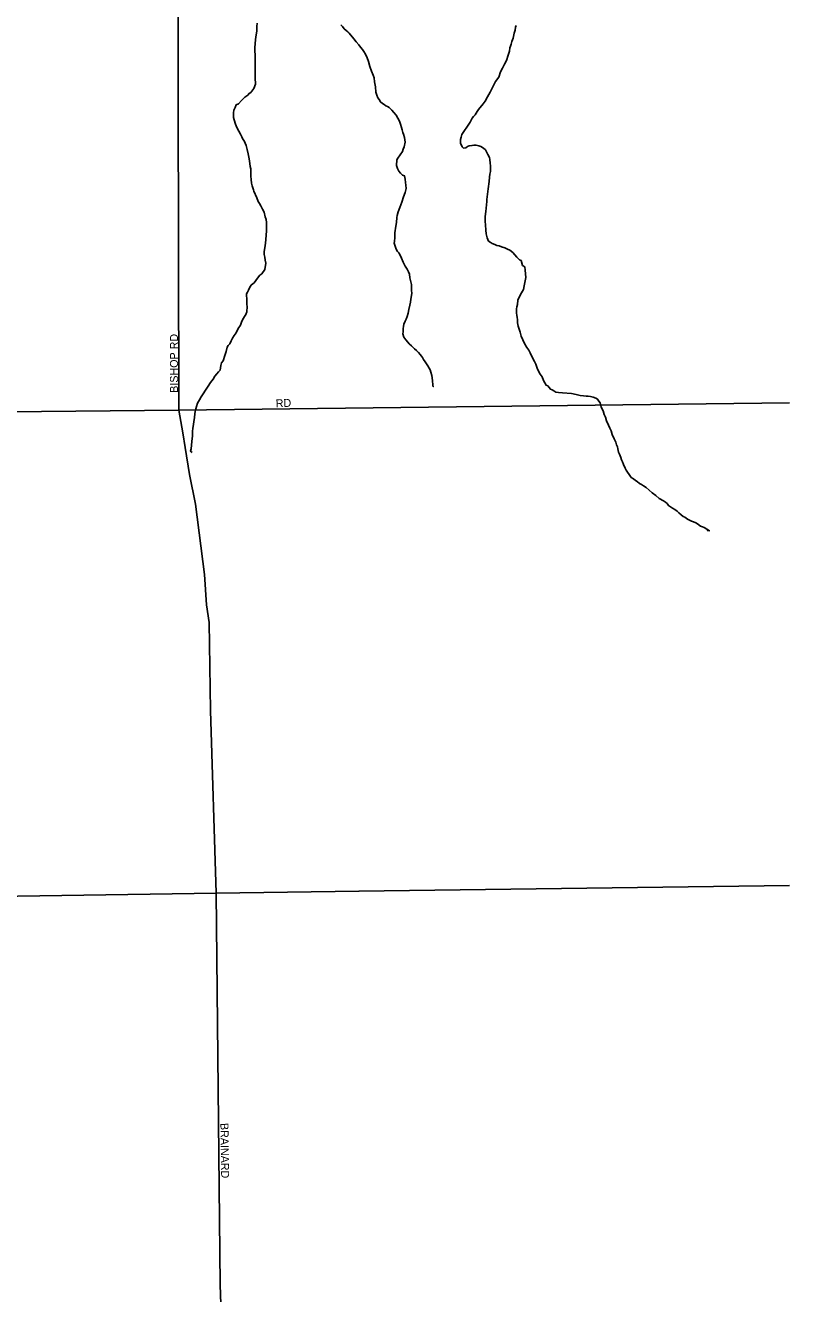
# Model space of a CAD drawing. Extents: x 2139079 to 2262683, y 1235796 to 1334992.
# Drawn here: x 2247339 to 2252112, y 1285350 to 1293274 of the extents above; entities that cross this region are included whole.
import ezdxf

# ---------------------------------------------------------------- set-up
doc = ezdxf.new("R2010")
doc.units = 0
for name, color, linetype in [('GM_X_City_Street', 7, 'Continuous'), ('GM_X_City_Street_Text', 7, 'Continuous'), ('GM_X_Minor_River', 7, 'Continuous')]:
    doc.layers.add(name, color=color, linetype=linetype)

msp = doc.modelspace()

# ---------------------------------------------------------------- linework, layer by layer
at = {"layer": 'GM_X_City_Street'}
msp.add_line((2249421.9, 1287863.7), (2252112.1, 1287899.2), dxfattribs=at)
for points in [[(2248297.3, 1290870.7), (2248287, 1295834.9), (2248278.5, 1302209.7)], [(2245720.1, 1290844.7), (2248297.3, 1290870.7), (2252112.1, 1290916.7)], [(2248530.3, 1287852), (2248496.2, 1288993.7), (2248487, 1289542.5), (2248471.2, 1289654.7), (2248457.5, 1289843), (2248402.3, 1290281.7), (2248364.6, 1290468), (2248336.9, 1290636.3), (2248323.1, 1290728.5), (2248297.3, 1290870.7)], [(2245775.2, 1287810.6), (2248530.3, 1287852), (2249421.9, 1287863.7), (2249421.9, 1287863.7)], [(2248907.5, 1283963.8), (2248885.1, 1284049.7), (2248872, 1284094.2), (2248838.9, 1284179.1), (2248713.4, 1284411.6), (2248617.1, 1284555), (2248589.2, 1284635.2), (2248581.4, 1284717.3), (2248573.6, 1284859.5), (2248556.5, 1285404.4), (2248530.3, 1287852)]]:
    msp.add_lwpolyline(points, dxfattribs=at)
at = {"layer": 'GM_X_Minor_River'}
for points in [[(2248787.1, 1293289), (2248785.3, 1293266.9), (2248783.6, 1293238.8), (2248779.9, 1293214.7), (2248776.2, 1293186.6), (2248774.5, 1293158.5), (2248772.8, 1293136.4), (2248773, 1293112.3), (2248773.3, 1293090.3), (2248773.6, 1293060.2), (2248774, 1293022.1), (2248774.6, 1292974), (2248775, 1292935.8), (2248777.2, 1292917.8), (2248777.3, 1292907.8), (2248765.6, 1292879.6), (2248747.9, 1292855.3), (2248735.9, 1292849.2), (2248728, 1292839.1)], [(2249310.1, 1293278.7), (2249320.3, 1293266.8), (2249330.4, 1293252.8), (2249342.6, 1293242.9), (2249352.7, 1293235), (2249360.8, 1293225.1), (2249391.3, 1293189.3), (2249405.5, 1293171.4), (2249421.7, 1293153.5), (2249431.9, 1293137.6), (2249444.1, 1293123.7), (2249452.2, 1293111.7), (2249462.4, 1293093.8)], [(2250404.1, 1293274.5), (2250400.2, 1293262.5), (2250398.4, 1293244.4), (2250392.6, 1293226.3), (2250384.9, 1293194.1), (2250377.2, 1293173.9), (2250373.3, 1293157.9), (2250369.5, 1293143.8), (2250365.6, 1293133.7), (2250361.8, 1293113.6)], [(2250361.8, 1293113.6), (2250354.1, 1293087.4), (2250344.4, 1293055.2), (2250330.7, 1293031), (2250318.9, 1293006.8), (2250307.1, 1292984.6), (2250295.5, 1292950.4), (2250275.8, 1292924.1), (2250260.1, 1292893.9), (2250242.5, 1292857.6), (2250224.8, 1292827.3), (2250211, 1292801.1), (2250199.2, 1292784.9), (2250189.3, 1292772.7), (2250177.4, 1292758.6), (2250169.6, 1292748.4), (2250159.7, 1292736.3), (2250147.9, 1292716.1), (2250138, 1292704), (2250130.1, 1292693.9), (2250116.3, 1292669.6), (2250104.5, 1292651.5), (2250073, 1292605), (2250065.1, 1292592.9), (2250061.3, 1292574.8), (2250057.5, 1292560.7), (2250055.7, 1292538.6), (2250066, 1292514.6), (2250076.1, 1292506.7), (2250090.1, 1292508.9), (2250100, 1292517), (2250110, 1292521.1), (2250128, 1292523.3), (2250140, 1292525.5), (2250154, 1292525.6), (2250172.1, 1292521.8), (2250184.2, 1292517.9), (2250200.3, 1292508.1), (2250212.4, 1292496.2), (2250226.8, 1292468.2), (2250237, 1292448.3), (2250239.2, 1292436.3), (2250241.4, 1292414.2), (2250243.6, 1292396.2), (2250243.8, 1292384.2), (2250244, 1292362.1), (2250240.2, 1292344), (2250238.4, 1292325.9), (2250234.7, 1292297.8), (2250229.2, 1292253.6), (2250221.9, 1292185.4), (2250220.1, 1292173.3), (2250218.3, 1292153.2), (2250216.5, 1292133.2), (2250214.8, 1292111.1), (2250211.1, 1292080.9), (2250211.5, 1292048.8), (2250211.7, 1292028.8), (2250214.1, 1291994.7), (2250216.3, 1291972.7), (2250222.6, 1291946.7), (2250226.7, 1291936.7), (2250230.8, 1291926.7), (2250240.9, 1291920.8), (2250255.1, 1291910.9), (2250271.2, 1291905.1), (2250283.2, 1291899.2), (2250297.3, 1291897.3), (2250313.4, 1291891.5), (2250333.5, 1291883.7), (2250349.6, 1291875.9), (2250365.7, 1291870), (2250383.9, 1291854.2), (2250396.1, 1291840.3), (2250408.3, 1291826.3), (2250424.5, 1291808.5), (2250434.6, 1291804.6), (2250442.9, 1291774.6), (2250459.1, 1291764.7), (2250461.3, 1291744.7), (2250463.8, 1291698.6), (2250454.4, 1291646.3), (2250450.6, 1291624.2), (2250436.8, 1291604), (2250425.1, 1291579.8), (2250415.3, 1291557.6), (2250411.6, 1291529.5), (2250407.8, 1291515.4), (2250405.9, 1291503.4), (2250406.1, 1291485.3), (2250406.2, 1291475.3), (2250408.3, 1291463.3), (2250410.5, 1291449.3), (2250412.6, 1291437.3), (2250412.9, 1291415.2), (2250417.1, 1291395.2), (2250423.3, 1291377.2), (2250429.6, 1291357.2), (2250435.8, 1291333.2), (2250446.1, 1291309.3), (2250456.4, 1291287.3)], [(2249462.4, 1293093.8), (2249472.7, 1293071.8), (2249483, 1293047.9), (2249491.3, 1293017.9), (2249501.7, 1292987.9), (2249512, 1292963.9), (2249518.2, 1292945.9), (2249520.5, 1292921.9), (2249524.8, 1292889.9), (2249527.2, 1292857.8), (2249533.4, 1292837.8), (2249539.6, 1292821.8), (2249547.8, 1292811.9), (2249557.9, 1292795.9), (2249570.1, 1292786), (2249580.2, 1292780.1), (2249590.3, 1292772.2), (2249600.3, 1292768.3), (2249610.4, 1292760.4), (2249628.7, 1292744.6), (2249640.8, 1292730.6), (2249655, 1292712.8), (2249665.3, 1292694.8), (2249675.5, 1292674.9), (2249681.7, 1292656.9), (2249688, 1292636.9), (2249692.1, 1292620.9), (2249696.3, 1292604.9), (2249700.4, 1292594.9), (2249706.7, 1292572.9), (2249711, 1292544.9), (2249705.4, 1292514.7), (2249699.5, 1292500.6), (2249693.7, 1292486.5), (2249679.9, 1292466.3), (2249666.1, 1292444.1), (2249658.2, 1292434), (2249656.6, 1292397.8), (2249662.8, 1292379.9), (2249671, 1292363.9), (2249681.1, 1292350), (2249695.3, 1292338.1), (2249707.4, 1292334.2), (2249711.6, 1292314.2), (2249713.9, 1292292.2), (2249716, 1292276.1), (2249716.3, 1292254.1), (2249710.6, 1292229.9), (2249700.8, 1292203.8), (2249691.2, 1292169.6), (2249677.5, 1292137.3), (2249667.8, 1292109.1), (2249660.1, 1292087), (2249658.2, 1292072.9), (2249656.6, 1292042.8), (2249652.8, 1292018.7), (2249647.2, 1291978.5), (2249645.6, 1291948.4), (2249643.8, 1291924.3), (2249642, 1291914.3), (2249646.1, 1291900.3), (2249654.4, 1291876.3), (2249662.6, 1291862.4), (2249670.7, 1291852.4), (2249680.9, 1291834.5), (2249687.1, 1291820.5), (2249699.4, 1291794.6), (2249711.7, 1291770.6), (2249723.9, 1291750.7), (2249732.1, 1291734.7), (2249738.3, 1291720.8), (2249740.6, 1291696.7), (2249751, 1291654.7), (2249751.2, 1291638.7), (2249751.5, 1291618.6), (2249751.7, 1291600.6), (2249749.8, 1291586.5), (2249746, 1291564.4), (2249744.3, 1291544.3), (2249740.5, 1291526.2), (2249734.8, 1291498.1), (2249729, 1291476), (2249723.2, 1291455.8), (2249717.4, 1291437.7), (2249711.5, 1291425.6), (2249703.7, 1291407.5), (2249699.9, 1291393.4), (2249698, 1291379.3), (2249698.3, 1291359.3), (2249696.4, 1291347.2), (2249702.7, 1291325.2), (2249714.8, 1291309.3), (2249727, 1291295.4), (2249735.1, 1291285.5), (2249751.3, 1291271.6), (2249769.6, 1291253.8), (2249781.7, 1291241.9), (2249793.9, 1291230), (2249804, 1291218), (2249812.1, 1291208.1), (2249820.3, 1291198.1)], [(2248728, 1292839.1), (2248710.1, 1292824.8), (2248688.3, 1292804.5), (2248670.5, 1292784.3), (2248654.6, 1292778.1), (2248648.7, 1292762), (2248640.9, 1292743.8), (2248639.1, 1292727.8), (2248639.2, 1292715.7), (2248639.4, 1292699.7), (2248643.6, 1292683.7), (2248651.9, 1292657.7), (2248660.2, 1292635.7), (2248672.4, 1292613.8), (2248682.7, 1292593.8), (2248690.9, 1292577.9), (2248697, 1292563.9), (2248705.2, 1292552), (2248711.4, 1292538), (2248717.5, 1292524), (2248723.8, 1292498), (2248730.1, 1292472), (2248736.5, 1292440), (2248740.8, 1292411.9), (2248743, 1292391.9), (2248747.2, 1292377.9), (2248747.4, 1292359.9), (2248747.5, 1292349.8), (2248747.7, 1292331.8), (2248749.9, 1292311.8), (2248752.2, 1292287.7), (2248756.4, 1292271.7), (2248760.6, 1292259.7), (2248764.7, 1292247.7), (2248766.8, 1292237.7), (2248785.3, 1292195.8), (2248793.6, 1292173.8), (2248801.7, 1292161.9), (2248809.9, 1292145.9), (2248820.1, 1292126), (2248830.4, 1292108), (2248836.7, 1292078), (2248842.9, 1292062), (2248845.1, 1292042), (2248845.3, 1292023.9), (2248845.7, 1291987.9), (2248842, 1291965.8), (2248840.3, 1291933.6), (2248836.7, 1291897.5), (2248831.1, 1291861.3), (2248831.3, 1291843.3), (2248835.5, 1291825.3), (2248837.7, 1291807.2), (2248840, 1291789.2), (2248834.4, 1291749), (2248816.7, 1291722.8), (2248802.7, 1291712.6), (2248788.9, 1291694.4), (2248767.2, 1291666.1), (2248751.3, 1291653.9), (2248743.4, 1291643.7), (2248731.7, 1291619.6), (2248725.8, 1291607.4), (2248719.9, 1291597.4), (2248722.4, 1291555.3), (2248722.6, 1291531.2), (2248724.8, 1291517.2), (2248723.1, 1291485.1), (2248715.3, 1291466.9), (2248707.5, 1291454.8), (2248701.6, 1291444.7), (2248691.8, 1291426.6), (2248682, 1291400.4), (2248668.2, 1291380.2), (2248656.5, 1291354), (2248642.7, 1291335.8), (2248632.8, 1291319.6), (2248625, 1291303.5), (2248615.2, 1291285.3), (2248605.3, 1291273.2), (2248599.4, 1291263.1), (2248593.7, 1291237), (2248584, 1291210.8), (2248574.3, 1291178.6), (2248564.4, 1291166.4), (2248560.6, 1291148.3), (2248554.9, 1291120.2), (2248545, 1291110.1), (2248535.1, 1291097.9), (2248523.3, 1291081.7), (2248511.5, 1291063.6), (2248495.7, 1291043.3), (2248479.9, 1291019.1), (2248464.2, 1290994.8), (2248450.4, 1290972.6), (2248436.6, 1290952.4), (2248426.8, 1290934.3), (2248415, 1290914.1), (2248407.2, 1290893.9), (2248403.4, 1290877.9), (2248399.5, 1290861.8)], [(2250456.4, 1291287.3), (2250470.7, 1291261.4), (2250482.9, 1291245.5), (2250491.1, 1291227.5), (2250509.6, 1291189.6), (2250519.8, 1291173.7), (2250528, 1291157.7), (2250538.3, 1291125.7), (2250554.7, 1291095.8), (2250566.9, 1291077.9), (2250575.2, 1291055.9), (2250591.5, 1291026), (2250601.6, 1291022.1), (2250617.9, 1291002.2), (2250629.9, 1290996.4), (2250640, 1290990.5), (2250652.1, 1290982.6), (2250668.2, 1290980.7), (2250694.2, 1290979), (2250750.4, 1290973.6), (2250778.5, 1290967.9), (2250804.6, 1290962.2), (2250824.7, 1290960.4), (2250840.7, 1290958.5), (2250854.8, 1290956.7), (2250868.8, 1290954.8), (2250884.9, 1290951), (2250901, 1290945.2), (2250913.1, 1290939.3), (2250921.2, 1290927.3), (2250929.4, 1290915.4), (2250935.7, 1290889.4), (2250948, 1290865.4), (2250954.2, 1290843.4), (2250962.4, 1290825.5), (2250968.7, 1290803.5), (2250981, 1290775.5), (2250989.2, 1290757.6), (2250997.4, 1290741.6), (2251003.7, 1290717.6), (2251016, 1290691.7), (2251026.3, 1290669.7), (2251030.5, 1290653.7), (2251036.6, 1290641.8), (2251038.8, 1290627.7), (2251043, 1290607.7), (2251049.2, 1290595.8), (2251057.4, 1290573.8), (2251061.6, 1290559.8), (2251067.7, 1290547.8), (2251073.9, 1290529.8), (2251084.2, 1290507.9), (2251090.3, 1290495.9), (2251100.5, 1290482), (2251110.7, 1290468.1), (2251122.9, 1290450.1), (2251137.1, 1290440.3), (2251149.2, 1290430.4), (2251159.3, 1290424.5), (2251175.4, 1290412.6), (2251187.5, 1290404.7), (2251199.6, 1290396.8), (2251215.8, 1290387), (2251254.2, 1290353.3), (2251276.4, 1290337.5), (2251296.7, 1290317.6), (2251324.9, 1290303.9), (2251337, 1290296), (2251347.1, 1290286.1), (2251355.3, 1290274.2), (2251367.4, 1290266.3), (2251381.5, 1290258.4), (2251395.6, 1290248.5), (2251409.8, 1290238.7), (2251419.9, 1290228.7), (2251434.1, 1290216.9), (2251448.2, 1290205), (2251458.3, 1290201.1), (2251474.4, 1290189.2), (2251486.5, 1290183.3), (2251498.6, 1290177.4), (2251512.7, 1290171.6), (2251526.8, 1290165.7), (2251536.9, 1290159.8), (2251555.1, 1290146), (2251567.2, 1290140.1), (2251579.2, 1290136.2), (2251579.2, 1290136.2), (2251611.5, 1290116.5), (2251597.5, 1290118.3), (2251611.5, 1290116.5)], [(2249820.3, 1291198.1), (2249826.4, 1291186.2), (2249836.6, 1291172.3), (2249844.7, 1291160.3), (2249852.9, 1291146.4), (2249861.1, 1291132.4), (2249867.2, 1291122.4), (2249871.4, 1291108.4), (2249877.6, 1291086.4), (2249882, 1291056.4), (2249884.3, 1291026.4), (2249886.4, 1291016.3), (2249886.4, 1291016.3)], [(2248399.5, 1290861.8), (2248397.7, 1290847.7), (2248396, 1290823.6), (2248384.7, 1290755.3), (2248382.9, 1290739.2), (2248383, 1290727.2), (2248383.2, 1290709.2), (2248379.6, 1290675), (2248374.1, 1290628.8), (2248370.3, 1290614.8), (2248370.3, 1290614.8), (2248380.4, 1290604.8)]]:
    msp.add_lwpolyline(points, dxfattribs=at)

# ---------------------------------------------------------------- texts
at = {"layer": 'GM_X_City_Street_Text'}
for s, rotation, p in [('BISHOP RD', 90, (2248292.3, 1290978.7)), ('RD', 3.01098, (2248904, 1290886.8)), ('BRAINARD', 270.78439, (2248557.3, 1286416))]:
    msp.add_text(s, height=50, rotation=rotation, dxfattribs=at).set_placement(p)

doc.saveas('drawing.dxf')
